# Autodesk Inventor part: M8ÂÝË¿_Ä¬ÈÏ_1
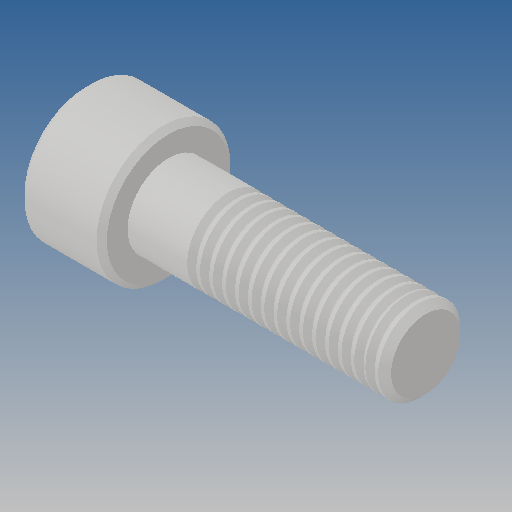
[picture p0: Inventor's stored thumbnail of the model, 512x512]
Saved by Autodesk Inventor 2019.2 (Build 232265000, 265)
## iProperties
Created: 2013-03
Part Number: M8ÂÝË¿_Ä¬ÈÏ_1
Material: Ogólny
Document SubType Name: Modeling
Designer: CADENGINEERING4
Density: 1 g/cm^3
Appearance: Domyślna
Author: CADENGINEERING4
Revision Number: ÈÎºÎ
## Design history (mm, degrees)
feature "NONE"
node "Bryła1"
